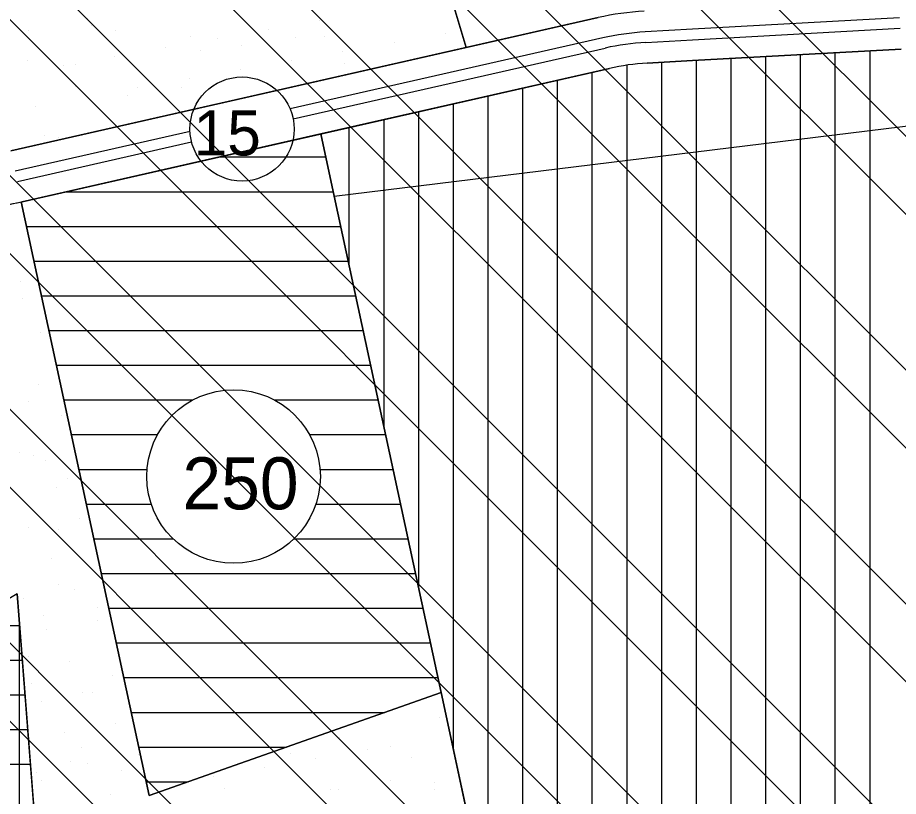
# Model space of a CAD drawing. Extents: x 409341 to 428634, y 4447481 to 4463281.
# Drawn here: x 420653.1 to 420906.8, y 4458119.5 to 4458343.9 of the extents above; entities that cross this region are included whole.
import ezdxf

# ---------------------------------------------------------------- set-up
doc = ezdxf.new("R2010")
doc.units = 0
for name, color, linetype in [('ADA', 7, 'Continuous'), ('ADAKENARI', 7, 'Continuous'), ('Default', 7, 'Continuous'), ('KALDIRIM', 7, 'Continuous'), ('KD_DAIRE', 7, 'Continuous'), ('KD_YGEN', 7, 'Continuous'), ('PL_AYA_PARK_DINLENME', 7, 'Continuous'), ('PL_K_AKARYAKIT_LPG_Y', 7, 'Continuous'), ('PL_KON_MEV_250', 7, 'Continuous'), ('PL_KON_ONE_250', 7, 'Continuous'), ('PL_SAY_SPOR', 7, 'Continuous'), ('SM_DAIRE', 7, 'Continuous'), ('SM_TAKS', 7, 'Continuous'), ('SN_TR_SIVILASMA', 7, 'Continuous'), ('TR_AKARYAKIT_SERVİS', 7, 'Continuous'), ('TR_ORTAGELISME', 7, 'Continuous'), ('TR_ORTAYOGUNKONUT', 7, 'Continuous'), ('TR_PARKALANI', 7, 'Continuous')]:
    doc.layers.add(name, color=color, linetype=linetype)

# ---------------------------------------------------------------- blocks, each defined once
blk = doc.blocks.new('POINT_DISPLAY')
at = {"layer": 'Default'}
blk.add_line((0, 0), (0, 0), dxfattribs=at)

msp = doc.modelspace()

# ---------------------------------------------------------------- linework, layer by layer
at = {"layer": 'ADA'}
for p, q in [((420782.34, 4458335.03), (420761.16, 4458405.89)), ((420744.27, 4458292.48), (420964.39, 4458319.42)), ((420744.27, 4458292.48), (420740.42, 4458310.37)), ((420775.05, 4458149.45), (420744.27, 4458292.48)), ((420690.92, 4458119.77), (420654.12, 4458290.77)), ((420652.94, 4458177.84), (420659.03, 4458099.33)), ((420690.92, 4458119.77), (420775.05, 4458149.45)), ((420795.15, 4458056.03), (420775.05, 4458149.45))]:
    msp.add_line(p, q, dxfattribs=at)
at = {"layer": 'ADAKENARI'}
for p, q in [((420820.25, 4458343.88), (420651.06, 4458305.46)), ((420847.49, 4458331.49), (420907.59, 4458334.83)), ((420834.36, 4458330.76), (420847.49, 4458331.49)), ((420654.38, 4458290.83), (420823.57, 4458329.25))]:
    msp.add_line(p, q, dxfattribs=at)
for centre, radius, start, end in [((420837.97, 4458265.86), 80, 93.1798, 102.7916), ((420837.97, 4458265.86), 65, 93.1798, 102.7916), ((420639.99, 4458354.22), 65, 270.7473, 282.7916)]:
    msp.add_arc(centre, radius, start, end, dxfattribs=at)
at = {"layer": 'KALDIRIM'}
for p, q in [((420907.09, 4458343.82), (420847.49, 4458340.5)), ((420847.49, 4458340.5), (420833.86, 4458339.75)), ((420847.49, 4458337.5), (420907.26, 4458340.82)), ((420821.58, 4458338.02), (420731.53, 4458317.58)), ((420834.03, 4458336.75), (420847.49, 4458337.5)), ((420732.41, 4458314.7), (420822.25, 4458335.1)), ((420702.72, 4458311.04), (420652.39, 4458299.61)), ((420653.05, 4458296.69), (420703.17, 4458308.06))]:
    msp.add_line(p, q, dxfattribs=at)
for radius in [74, 71]:
    msp.add_arc((420837.97, 4458265.86), radius, 93.1798, 102.7916, dxfattribs=at)
at = {"layer": 'KD_DAIRE'}
msp.add_circle((420717.7, 4458311.78), 15, dxfattribs=at)
at = {"layer": 'PL_AYA_PARK_DINLENME'}
for p, q in [((420690.92, 4458119.77), (420654.12, 4458290.77)), ((420652.94, 4458177.84), (420659.03, 4458099.33)), ((420775.05, 4458149.45), (420690.92, 4458119.77)), ((420795.15, 4458056.03), (420775.05, 4458149.45))]:
    msp.add_line(p, q, dxfattribs=at)
for points in [[(420651.06, 4458305.46), (420782.27, 4458335.25), (420761.16, 4458405.89), (420743.03, 4458396.67), (420723.36, 4458386.67), (420703.69, 4458376.67), (420677.56, 4458363.39), (420677.32, 4458364.26), (420677.24, 4458364.55), (420623.66, 4458351.01), (420632.89, 4458304.12)], [(420654.12, 4458290.77), (420654.12, 4458290.77)]]:
    msp.add_lwpolyline(points, dxfattribs=at)
msp.add_arc((420639.99, 4458354.22), 65, 273.789, 282.552, dxfattribs=at)
at = {"layer": 'PL_K_AKARYAKIT_LPG_Y'}
msp.add_lwpolyline([(420616.54, 4458156.78), (420611.4, 4458153.8), (420606.54, 4458150.99), (420598.33, 4458146.24), (420599.93, 4458143.63), (420635.42, 4458085.67), (420659.03, 4458099.33), (420652.94, 4458177.84), (420646.54, 4458174.14), (420645.95, 4458173.8), (420636.54, 4458168.36), (420628.67, 4458163.8), (420626.54, 4458162.57), (420616.54, 4458156.78)], dxfattribs=at)
at = {"layer": 'PL_KON_MEV_250'}
for points in [[(420907.59, 4458334.83), (420847.49, 4458331.49), (420834.36, 4458330.76)], [(420823.57, 4458329.25), (420740.42, 4458310.37), (420744.27, 4458292.48), (420775.05, 4458149.45), (420795.15, 4458056.03), (420722.25, 4458040.54), (420669.86, 4458029.4)]]:
    msp.add_lwpolyline(points, dxfattribs=at)
msp.add_arc((420837.97, 4458265.86), 65, 93.1798, 102.7916, dxfattribs=at)
at = {"layer": 'PL_KON_ONE_250'}
for p, q in [((420740.42, 4458310.37), (420654.38, 4458290.83)), ((420744.27, 4458292.48), (420740.42, 4458310.37)), ((420775.05, 4458149.45), (420744.27, 4458292.48)), ((420654.12, 4458290.77), (420690.92, 4458119.77)), ((420690.92, 4458119.77), (420775.05, 4458149.45))]:
    msp.add_line(p, q, dxfattribs=at)
msp.add_lwpolyline([(420654.12, 4458290.77), (420654.12, 4458290.77)], dxfattribs=at)
msp.add_arc((420639.99, 4458354.22), 65, 282.552, 282.7916, dxfattribs=at)
at = {"layer": 'PL_SAY_SPOR'}
for p, q in [((420761.16, 4458405.89), (420782.27, 4458335.25)), ((420782.27, 4458335.25), (420820.25, 4458343.88))]:
    msp.add_line(p, q, dxfattribs=at)
msp.add_arc((420837.97, 4458265.86), 80, 93.1798, 102.7916, dxfattribs=at)
at = {"layer": 'SM_DAIRE'}
msp.add_circle((420715.26, 4458211.66), 25, dxfattribs=at)
at = {"layer": 'SN_TR_SIVILASMA'}
for p, q in [((420847.49, 4458303.74), (420679.79, 4458471.44)), ((420847.49, 4458281.29), (420672.1, 4458456.69)), ((420847.49, 4458236.39), (420656.7, 4458427.18)), ((420847.49, 4458213.94), (420649.01, 4458412.43)), ((420847.49, 4458169.04), (420633.61, 4458382.92)), ((421296.89, 4457921.7), (420847.49, 4458371.1)), ((420847.49, 4458146.59), (420625.91, 4458368.17)), ((421296.66, 4457899.48), (420847.49, 4458348.64)), ((420805.55, 4458143.63), (420610.52, 4458338.66)), ((420783.1, 4458143.63), (420602.82, 4458323.91)), ((421296.19, 4457855.04), (420847.49, 4458303.74)), ((420738.2, 4458143.63), (420581.75, 4458300.08)), ((420715.75, 4458143.63), (420570.53, 4458288.85)), ((421295.96, 4457832.82), (420847.49, 4458281.29)), ((420670.85, 4458143.63), (420548.07, 4458266.4)), ((421295.5, 4457788.39), (420847.49, 4458236.39)), ((421285.81, 4457775.62), (420847.49, 4458213.94)), ((421240.43, 4457776.1), (420847.49, 4458169.04)), ((421217.74, 4457776.34), (420847.49, 4458146.59)), ((421013.52, 4457778.5), (420648.4, 4458143.63)), ((421036.21, 4457778.26), (420670.85, 4458143.63)), ((420828.4, 4458030.98), (420715.75, 4458143.63)), ((420841.86, 4458039.97), (420738.2, 4458143.63)), ((421149.66, 4457777.06), (420783.1, 4458143.63)), ((421172.36, 4457776.82), (420805.55, 4458143.63))]:
    msp.add_line(p, q, dxfattribs=at)
at = {"layer": 'TR_AKARYAKIT_SERVİS'}
for p, q in [((420653.59, 4458096.19), (420653.59, 4458169.48)), ((420637.28, 4458168.79), (420653.64, 4458168.79)), ((420620.01, 4458158.79), (420654.41, 4458158.79)), ((420646.37, 4458148.79), (420655.19, 4458148.79)), ((420646.37, 4458138.79), (420655.97, 4458138.79)), ((420646.37, 4458128.79), (420656.74, 4458128.79))]:
    msp.add_line(p, q, dxfattribs=at)
msp.add_lwpolyline([(420636.54, 4458168.36), (420628.67, 4458163.8), (420626.54, 4458162.57), (420616.54, 4458156.78), (420611.4, 4458153.8), (420606.54, 4458150.99), (420598.33, 4458146.24), (420599.93, 4458143.63), (420635.42, 4458085.67), (420659.03, 4458099.33), (420652.94, 4458177.84), (420646.54, 4458174.14), (420645.95, 4458173.8), (420636.54, 4458168.36)], dxfattribs=at)
at = {"layer": 'TR_ORTAGELISME'}
for p, q in [((420711.19, 4458303.73), (420741.85, 4458303.73)), ((420667.15, 4458293.73), (420744, 4458293.73)), ((420655.63, 4458283.73), (420746.16, 4458283.73)), ((420657.78, 4458273.73), (420748.31, 4458273.73)), ((420659.94, 4458263.73), (420750.46, 4458263.73)), ((420662.09, 4458253.73), (420752.61, 4458253.73)), ((420664.24, 4458243.73), (420754.76, 4458243.73)), ((420666.39, 4458233.73), (420703.53, 4458233.73)), ((420727, 4458233.73), (420756.91, 4458233.73)), ((420668.55, 4458223.73), (420693.37, 4458223.73)), ((420737.15, 4458223.73), (420759.07, 4458223.73)), ((420670.7, 4458213.73), (420690.35, 4458213.73)), ((420740.18, 4458213.73), (420761.22, 4458213.73)), ((420672.85, 4458203.73), (420691.55, 4458203.73)), ((420738.97, 4458203.73), (420763.37, 4458203.73)), ((420675, 4458193.73), (420697.84, 4458193.73)), ((420732.69, 4458193.73), (420765.52, 4458193.73)), ((420677.16, 4458183.73), (420767.67, 4458183.73)), ((420679.31, 4458173.73), (420769.82, 4458173.73)), ((420681.46, 4458163.73), (420771.97, 4458163.73)), ((420683.61, 4458153.73), (420774.13, 4458153.73)), ((420685.76, 4458143.73), (420758.83, 4458143.73)), ((420687.92, 4458133.73), (420730.49, 4458133.73)), ((420690.07, 4458123.73), (420702.15, 4458123.73))]:
    msp.add_line(p, q, dxfattribs=at)
at = {"layer": 'TR_ORTAYOGUNKONUT'}
for p, q in [((420858.59, 4458038.58), (420858.59, 4458332.11)), ((420868.59, 4458030.37), (420868.59, 4458332.66)), ((420878.59, 4457779.93), (420878.59, 4458333.22)), ((420888.59, 4457779.82), (420888.59, 4458333.77)), ((420898.59, 4457779.72), (420898.59, 4458334.33)), ((420828.59, 4458031.22), (420828.59, 4458330.18)), ((420838.59, 4458038.86), (420838.59, 4458331)), ((420848.59, 4458040.81), (420848.59, 4458331.55)), ((420818.59, 4457786.47), (420818.59, 4458328.12)), ((420808.59, 4457802.8), (420808.59, 4458325.85)), ((420798.59, 4457819.14), (420798.59, 4458323.58)), ((420788.59, 4458086.5), (420788.59, 4458321.3)), ((420768.59, 4458179.46), (420768.59, 4458316.76)), ((420778.59, 4458132.98), (420778.59, 4458319.03)), ((420758.59, 4458225.94), (420758.59, 4458314.49)), ((420748.59, 4458272.42), (420748.59, 4458312.22))]:
    msp.add_line(p, q, dxfattribs=at)
for points in [[(420907.59, 4458334.83), (420847.49, 4458331.49), (420834.36, 4458330.76)], [(420823.57, 4458329.25), (420740.42, 4458310.37), (420744.27, 4458292.48), (420775.05, 4458149.45)], [(420775.05, 4458149.45), (420795.15, 4458056.03), (420722.25, 4458040.54), (420669.86, 4458029.4), (420822.23, 4457780.52)]]:
    msp.add_lwpolyline(points, dxfattribs=at)
msp.add_arc((420837.97, 4458265.86), 65, 93.1798, 102.7916, dxfattribs=at)

# ---------------------------------------------------------------- block references
at = {"layer": 'TR_PARKALANI', "xscale": 0.1, "yscale": 0.10000000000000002}
for p in [(420673.27, 4458343.71), (420673.27, 4458343.71), (420740.11, 4458343.02), (420740.11, 4458343.02), (420740.11, 4458343.02), (420740.11, 4458343.02), (420656.28, 4458340.23), (420656.28, 4458340.23), (420674.36, 4458341.58), (420674.36, 4458341.58), (420674.36, 4458341.58), (420674.36, 4458341.58), (420681.29, 4458340.06), (420681.29, 4458340.06), (420725.34, 4458340.42), (420725.34, 4458340.42), (420725.34, 4458340.42), (420725.34, 4458340.42), (420702.82, 4458338.5), (420702.82, 4458338.5), (420710.57, 4458337.81), (420710.57, 4458337.81), (420710.57, 4458337.81), (420710.57, 4458337.81), (420733.23, 4458338.22), (420733.23, 4458338.22), (420741.47, 4458338.35), (420741.47, 4458338.35), (420741.47, 4458338.35), (420741.47, 4458338.35), (420776.31, 4458339.25), (420776.31, 4458339.25), (420776.31, 4458339.25), (420776.31, 4458339.25), (420695.79, 4458335.21), (420695.79, 4458335.21), (420695.79, 4458335.21), (420695.79, 4458335.21), (420705.64, 4458334.38), (420705.64, 4458334.38), (420705.64, 4458334.38), (420705.64, 4458334.38), (420717.59, 4458335.9), (420717.59, 4458335.9), (420761.54, 4458336.65), (420761.54, 4458336.65), (420761.54, 4458336.65), (420761.54, 4458336.65), (420681.02, 4458332.6), (420681.02, 4458332.6), (420681.02, 4458332.6), (420681.02, 4458332.6), (420746.77, 4458334.04), (420746.77, 4458334.04), (420746.77, 4458334.04), (420746.77, 4458334.04), (420655.89, 4458331.54), (420655.89, 4458331.54), (420666.25, 4458330), (420666.25, 4458330), (420666.25, 4458330), (420666.25, 4458330), (420669.8, 4458330.42), (420669.8, 4458330.42), (420669.8, 4458330.42), (420669.8, 4458330.42), (420732, 4458331.44), (420732, 4458331.44), (420732, 4458331.44), (420732, 4458331.44), (420747.13, 4458330.69), (420747.13, 4458330.69), (420717.23, 4458328.83), (420717.23, 4458328.83), (420717.23, 4458328.83), (420717.23, 4458328.83), (420702.45, 4458326.23), (420702.45, 4458326.23), (420702.45, 4458326.23), (420702.45, 4458326.23), (420669.8, 4458324.02), (420669.8, 4458324.02), (420687.68, 4458323.62), (420687.68, 4458323.62), (420687.68, 4458323.62), (420687.68, 4458323.62), (420700.21, 4458323.73), (420700.21, 4458323.73), (420672.91, 4458321.02), (420672.91, 4458321.02), (420672.91, 4458321.02), (420672.91, 4458321.02), (420684.57, 4458321.41), (420684.57, 4458321.41), (420658.14, 4458318.41), (420658.14, 4458318.41), (420658.14, 4458318.41), (420658.14, 4458318.41), (420660.91, 4458309.9), (420660.91, 4458309.9), (420664.8, 4458309.43), (420664.8, 4458309.43), (420664.8, 4458309.43), (420664.8, 4458309.43), (420653.82, 4458267.71), (420653.82, 4458267.71), (420654.42, 4458262.98), (420654.42, 4458262.98), (420659.63, 4458253.07), (420659.03, 4458238.17), (420659.03, 4458238.17), (420656.16, 4458233.37), (420665.69, 4458229.19), (420665.69, 4458229.19), (420653.55, 4458218.6), (420657.58, 4458217.6), (420657.58, 4458217.6), (420660.98, 4458216.27), (420667.46, 4458211.07), (420664.24, 4458208.62), (420664.24, 4458208.62), (420670.9, 4458199.64), (420670.9, 4458199.64), (420656.13, 4458197.04), (420656.13, 4458197.04), (420664.85, 4458196.3), (420662.79, 4458188.06), (420662.79, 4458188.06), (420664.94, 4458180.43), (420664.94, 4458180.43), (420669.45, 4458179.08), (420669.45, 4458179.08), (420654.68, 4458176.47), (420654.68, 4458176.47), (420676.15, 4458174), (420660.51, 4458171.68), (420676.11, 4458170.1), (420676.11, 4458170.1), (420661.34, 4458167.49), (420661.34, 4458167.49), (420656.05, 4458159.92), (420668, 4458158.51), (420668, 4458158.51), (420657.04, 4458151.98), (420680.4, 4458154.24), (420680.4, 4458154.24), (420671.81, 4458149.38), (420674.66, 4458149.53), (420674.66, 4458149.53), (420659.89, 4458146.93), (420659.89, 4458146.93), (420774.69, 4458142.18), (420774.69, 4458142.18), (420681.32, 4458140.55), (420681.32, 4458140.55), (420666.55, 4458137.95), (420666.55, 4458137.95), (420745.67, 4458136.36), (420671.5, 4458133.72), (420687.98, 4458131.57), (420687.98, 4458131.57), (420731.69, 4458132.01), (420731.69, 4458132.01), (420753.73, 4458133.01), (420753.73, 4458133.01), (420760.44, 4458133.75), (420668.34, 4458129.68), (420673.21, 4458128.97), (420673.21, 4458128.97), (420738.96, 4458130.41), (420738.96, 4458130.41), (420766.58, 4458130.59), (420766.58, 4458130.59), (420658.44, 4458126.37), (420658.44, 4458126.37), (420683.11, 4458127.08), (420724.19, 4458127.8), (420724.19, 4458127.8), (420660.01, 4458124.08), (420660.01, 4458124.08), (420709.41, 4458125.2), (420709.41, 4458125.2), (420760.39, 4458124.03), (420760.39, 4458124.03), (420712.65, 4458121.87), (420743.07, 4458121.58), (420745.62, 4458121.43), (420745.62, 4458121.43), (420773.09, 4458123.47), (420773.24, 4458121.61), (420773.24, 4458121.61), (420679.87, 4458119.99), (420679.87, 4458119.99)]:
    msp.add_blockref('POINT_DISPLAY', p, dxfattribs=at)

# ---------------------------------------------------------------- texts
at = {"layer": 'KD_YGEN'}
msp.add_text('15', height=13, dxfattribs=at).set_placement((420703.77, 4458304.16))
at = {"layer": 'SM_TAKS'}
msp.add_text('250', height=15, dxfattribs=at).set_placement((420700.52, 4458202.21))

doc.saveas('drawing.dxf')
